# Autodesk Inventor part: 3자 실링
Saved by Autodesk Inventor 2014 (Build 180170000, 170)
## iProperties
Created: 2026-09
Part Number: 3자 실링
Material: 일반
Document SubType Name: Modeling
Designer: dg
Density: 1 g/cm^3
Appearance: 기본값
Author: dg
Author: jhkim
Creation Date: 2026-08-26
Sending System: Autodesk Inventor 2027
Preprocessor: ST-DEVELOPER v20.1
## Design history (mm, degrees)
node "3자 실링1"
node "솔리드1"
node "기준1"
